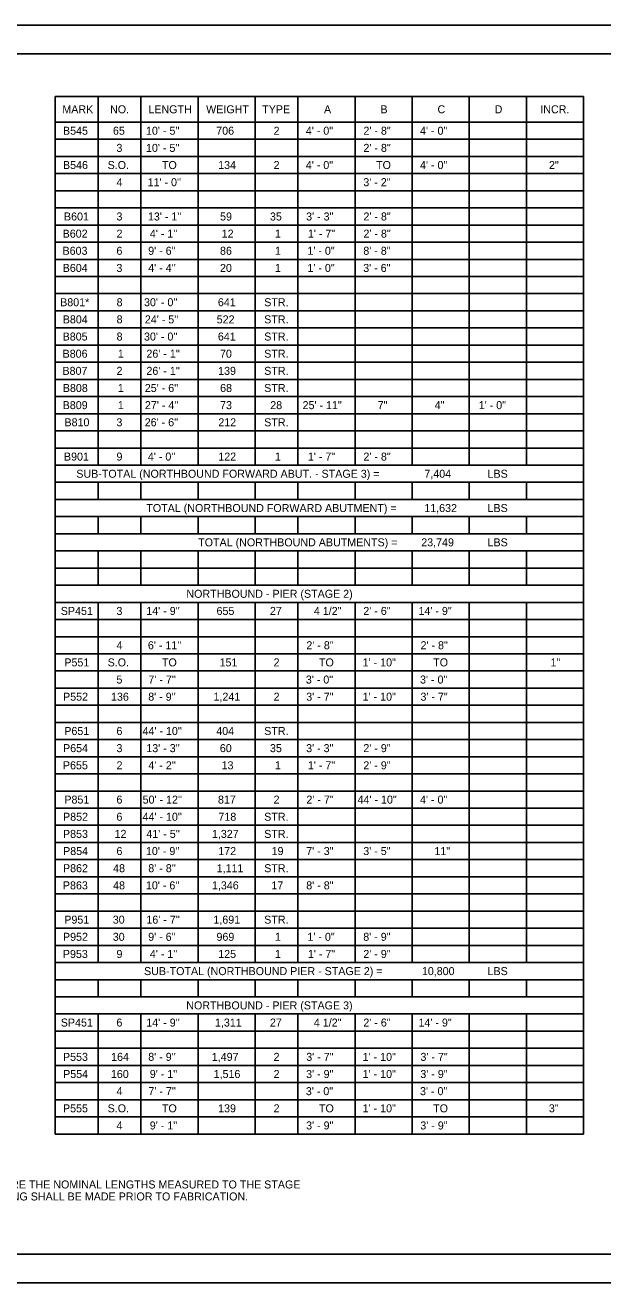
# Model space of a CAD drawing. Extents: x 1485751 to 1485785, y 230696.6 to 230718.6.
# Drawn here: x 1485763.13 to 1485773.25, y 230696.64 to 230718.64 of the extents above; entities that cross this region are included whole.
import ezdxf

# ---------------------------------------------------------------- set-up
doc = ezdxf.new("R2010")
doc.units = 0
for name, color, linetype in [('SH_Border', 7, 'Continuous'), ('SH_Cut_Line', 7, 'Continuous'), ('TX_P_Misc', 7, 'Continuous')]:
    doc.layers.add(name, color=color, linetype=linetype)

msp = doc.modelspace()

# ---------------------------------------------------------------- linework, layer by layer
at = {"layer": 'SH_Border'}
msp.add_lwpolyline([(1485753.033, 230718.141), (1485784.533, 230718.141), (1485784.533, 230697.141), (1485753.033, 230697.141)], close=True, dxfattribs=at)
at = {"layer": 'SH_Cut_Line'}
msp.add_lwpolyline([(1485751.033, 230718.641), (1485785.033, 230718.641), (1485785.033, 230696.641), (1485751.033, 230696.641)], close=True, dxfattribs=at)
at = {"layer": 'TX_P_Misc'}
for p, q in [((1485763.658, 230717.394), (1485772.908, 230717.394)), ((1485763.658, 230717.394), (1485763.658, 230699.244)), ((1485764.408, 230717.394), (1485764.408, 230710.944)), ((1485765.158, 230717.394), (1485765.158, 230710.944)), ((1485766.158, 230717.394), (1485766.158, 230710.944)), ((1485767.158, 230717.394), (1485767.158, 230710.944)), ((1485767.908, 230717.394), (1485767.908, 230710.944)), ((1485768.908, 230717.394), (1485768.908, 230710.944)), ((1485769.908, 230717.394), (1485769.908, 230710.944)), ((1485770.908, 230717.394), (1485770.908, 230710.944)), ((1485771.908, 230717.394), (1485771.908, 230710.944)), ((1485772.908, 230717.394), (1485772.908, 230699.244)), ((1485763.658, 230716.944), (1485772.908, 230716.944)), ((1485763.658, 230716.644), (1485772.908, 230716.644)), ((1485763.658, 230716.344), (1485772.908, 230716.344)), ((1485763.658, 230716.044), (1485772.908, 230716.044)), ((1485763.658, 230715.744), (1485772.908, 230715.744)), ((1485763.658, 230715.444), (1485772.908, 230715.444)), ((1485763.658, 230715.144), (1485772.908, 230715.144)), ((1485763.658, 230714.844), (1485772.908, 230714.844)), ((1485763.658, 230714.544), (1485772.908, 230714.544)), ((1485763.658, 230714.244), (1485772.908, 230714.244)), ((1485763.658, 230713.944), (1485772.908, 230713.944)), ((1485763.658, 230713.644), (1485772.908, 230713.644)), ((1485763.658, 230713.344), (1485772.908, 230713.344)), ((1485763.658, 230713.044), (1485772.908, 230713.044)), ((1485763.658, 230712.744), (1485772.908, 230712.744)), ((1485763.658, 230712.444), (1485772.908, 230712.444)), ((1485763.658, 230712.144), (1485772.908, 230712.144)), ((1485763.658, 230711.844), (1485772.908, 230711.844)), ((1485763.658, 230711.544), (1485772.908, 230711.544)), ((1485763.658, 230711.244), (1485772.908, 230711.244)), ((1485763.658, 230710.944), (1485772.908, 230710.944)), ((1485763.658, 230710.644), (1485772.908, 230710.644)), ((1485764.408, 230710.644), (1485764.408, 230710.344)), ((1485765.158, 230710.644), (1485765.158, 230710.344)), ((1485766.158, 230710.644), (1485766.158, 230710.344)), ((1485767.158, 230710.644), (1485767.158, 230710.344)), ((1485767.908, 230710.644), (1485767.908, 230710.344)), ((1485768.908, 230710.644), (1485768.908, 230710.344)), ((1485769.908, 230710.644), (1485769.908, 230710.344)), ((1485770.908, 230710.644), (1485770.908, 230710.344)), ((1485771.908, 230710.644), (1485771.908, 230710.344)), ((1485763.658, 230710.344), (1485772.908, 230710.344)), ((1485763.658, 230710.044), (1485772.908, 230710.044)), ((1485764.408, 230710.044), (1485764.408, 230709.744)), ((1485765.158, 230710.044), (1485765.158, 230709.744)), ((1485766.158, 230710.044), (1485766.158, 230709.744)), ((1485767.158, 230710.044), (1485767.158, 230709.744)), ((1485767.908, 230710.044), (1485767.908, 230709.744)), ((1485768.908, 230710.044), (1485768.908, 230709.744)), ((1485769.908, 230710.044), (1485769.908, 230709.744)), ((1485770.908, 230710.044), (1485770.908, 230709.744)), ((1485771.908, 230710.044), (1485771.908, 230709.744)), ((1485763.658, 230709.744), (1485772.908, 230709.744)), ((1485763.658, 230709.444), (1485772.908, 230709.444)), ((1485764.408, 230709.444), (1485764.408, 230708.844)), ((1485765.158, 230709.444), (1485765.158, 230708.844)), ((1485766.158, 230709.444), (1485766.158, 230708.844)), ((1485767.158, 230709.444), (1485767.158, 230708.844)), ((1485767.908, 230709.444), (1485767.908, 230708.844)), ((1485768.908, 230709.444), (1485768.908, 230708.844)), ((1485769.908, 230709.444), (1485769.908, 230708.844)), ((1485770.908, 230709.444), (1485770.908, 230708.844)), ((1485771.908, 230709.444), (1485771.908, 230708.844)), ((1485763.658, 230709.144), (1485772.908, 230709.144)), ((1485763.658, 230708.844), (1485772.908, 230708.844)), ((1485763.658, 230708.544), (1485772.908, 230708.544)), ((1485764.408, 230708.544), (1485764.408, 230702.244)), ((1485765.158, 230708.544), (1485765.158, 230702.244)), ((1485766.158, 230708.544), (1485766.158, 230702.244)), ((1485767.158, 230708.544), (1485767.158, 230702.244)), ((1485767.908, 230708.544), (1485767.908, 230702.244)), ((1485768.908, 230708.544), (1485768.908, 230702.244)), ((1485769.908, 230708.544), (1485769.908, 230702.244)), ((1485770.908, 230708.544), (1485770.908, 230702.244)), ((1485771.908, 230708.544), (1485771.908, 230702.244)), ((1485763.658, 230708.244), (1485772.908, 230708.244)), ((1485763.658, 230707.944), (1485772.908, 230707.944)), ((1485763.658, 230707.644), (1485772.908, 230707.644)), ((1485763.658, 230707.344), (1485772.908, 230707.344)), ((1485763.658, 230707.044), (1485772.908, 230707.044)), ((1485763.658, 230706.744), (1485772.908, 230706.744)), ((1485763.658, 230706.444), (1485772.908, 230706.444)), ((1485763.658, 230706.144), (1485772.908, 230706.144)), ((1485763.658, 230705.844), (1485772.908, 230705.844)), ((1485763.658, 230705.544), (1485772.908, 230705.544)), ((1485763.658, 230705.244), (1485772.908, 230705.244)), ((1485763.658, 230704.944), (1485772.908, 230704.944)), ((1485763.658, 230704.644), (1485772.908, 230704.644)), ((1485763.658, 230704.344), (1485772.908, 230704.344)), ((1485763.658, 230704.044), (1485772.908, 230704.044)), ((1485763.658, 230703.744), (1485772.908, 230703.744)), ((1485763.658, 230703.444), (1485772.908, 230703.444)), ((1485763.658, 230703.144), (1485772.908, 230703.144)), ((1485763.658, 230702.844), (1485772.908, 230702.844)), ((1485763.658, 230702.544), (1485772.908, 230702.544)), ((1485763.658, 230702.244), (1485772.908, 230702.244)), ((1485763.658, 230701.944), (1485772.908, 230701.944)), ((1485764.408, 230701.944), (1485764.408, 230701.644)), ((1485765.158, 230701.944), (1485765.158, 230701.644)), ((1485766.158, 230701.944), (1485766.158, 230701.644)), ((1485767.158, 230701.944), (1485767.158, 230701.644)), ((1485767.908, 230701.944), (1485767.908, 230701.644)), ((1485768.908, 230701.944), (1485768.908, 230701.644)), ((1485769.908, 230701.944), (1485769.908, 230701.644)), ((1485770.908, 230701.944), (1485770.908, 230701.644)), ((1485771.908, 230701.944), (1485771.908, 230701.644)), ((1485763.658, 230701.644), (1485772.908, 230701.644)), ((1485763.658, 230701.344), (1485772.908, 230701.344)), ((1485764.408, 230701.344), (1485764.408, 230699.244)), ((1485765.158, 230701.344), (1485765.158, 230699.244)), ((1485766.158, 230701.344), (1485766.158, 230699.244)), ((1485767.158, 230701.344), (1485767.158, 230699.244)), ((1485767.908, 230701.344), (1485767.908, 230699.244)), ((1485768.908, 230701.344), (1485768.908, 230699.244)), ((1485769.908, 230701.344), (1485769.908, 230699.244)), ((1485770.908, 230701.344), (1485770.908, 230699.244)), ((1485771.908, 230701.344), (1485771.908, 230699.244)), ((1485763.658, 230701.044), (1485772.908, 230701.044)), ((1485763.658, 230700.744), (1485772.908, 230700.744)), ((1485763.658, 230700.444), (1485772.908, 230700.444)), ((1485763.658, 230700.144), (1485772.908, 230700.144)), ((1485763.658, 230699.844), (1485772.908, 230699.844)), ((1485763.658, 230699.544), (1485772.908, 230699.544)), ((1485763.658, 230699.244), (1485772.908, 230699.244))]:
    msp.add_line(p, q, dxfattribs=at)

# ---------------------------------------------------------------- texts
for s, p in [('MARK', (1485763.782, 230717.099)), ('NO.', (1485764.618, 230717.099)), ('LENGTH', (1485765.288, 230717.099)), ('WEIGHT', (1485766.3, 230717.099)), ('TYPE', (1485767.282, 230717.099)), ('A', (1485768.364, 230717.099)), ('B', (1485769.353, 230717.099)), ('C', (1485770.352, 230717.099)), ('D', (1485771.353, 230717.099)), ('INCR.', (1485772.152, 230717.099)), ('B545', (1485763.793, 230716.724)), ('65', (1485764.668, 230716.724)), ("10' - 5''", (1485765.247, 230716.724)), ('706', (1485766.477, 230716.724)), ('2', (1485767.481, 230716.724)), ('4\' - 0"', (1485768.046, 230716.724)), ('2\' - 8"', (1485769.055, 230716.724)), ('4\' - 0"', (1485770.046, 230716.724)), ('3', (1485764.729, 230716.424)), ("10' - 5''", (1485765.247, 230716.424)), ('2\' - 8"', (1485769.055, 230716.424)), ('B546', (1485763.793, 230716.124)), ('S.O.', (1485764.575, 230716.124)), ('TO', (1485765.526, 230716.124)), ('134', (1485766.511, 230716.124)), ('2', (1485767.481, 230716.124)), ('4\' - 0"', (1485768.046, 230716.124)), ('TO', (1485769.276, 230716.124)), ('4\' - 0"', (1485770.046, 230716.124)), (' 2"', (1485772.252, 230716.124)), ('4', (1485764.731, 230715.824)), ("11' - 0''", (1485765.275, 230715.824)), ('3\' - 2"', (1485769.053, 230715.824)), ('B601', (1485763.81, 230715.224)), ('3', (1485764.729, 230715.224)), ("13' - 1''", (1485765.28, 230715.224)), ('59', (1485766.544, 230715.224)), ('35', (1485767.418, 230715.224)), ('3\' - 3"', (1485768.051, 230715.224)), ('2\' - 8"', (1485769.055, 230715.224)), ('B602', (1485763.787, 230714.924)), ('2', (1485764.731, 230714.924)), ("4' - 1''", (1485765.314, 230714.924)), ('12', (1485766.572, 230714.924)), ('1', (1485767.504, 230714.924)), ('1\' - 7"', (1485768.082, 230714.924)), ('2\' - 8"', (1485769.055, 230714.924)), ('B603', (1485763.785, 230714.624)), ('6', (1485764.729, 230714.624)), ("9' - 6''", (1485765.285, 230714.624)), ('86', (1485766.543, 230714.624)), ('1', (1485767.504, 230714.624)), ('1\' - 0"', (1485768.074, 230714.624)), ('8\' - 8"', (1485769.053, 230714.624)), ('B604', (1485763.788, 230714.324)), ('3', (1485764.729, 230714.324)), ("4' - 4''", (1485765.286, 230714.324)), ('20', (1485766.543, 230714.324)), ('1', (1485767.504, 230714.324)), ('1\' - 0"', (1485768.074, 230714.324)), ('3\' - 6"', (1485769.051, 230714.324)), ('B801*', (1485763.743, 230713.724)), ('8', (1485764.732, 230713.724)), ("30' - 0''", (1485765.212, 230713.724)), ('641', (1485766.506, 230713.724)), ('STR.', (1485767.317, 230713.724)), ('B804', (1485763.789, 230713.424)), ('8', (1485764.732, 230713.424)), ("24' - 5''", (1485765.227, 230713.424)), ('522', (1485766.485, 230713.424)), ('STR.', (1485767.317, 230713.424)), ('B805', (1485763.787, 230713.124)), ('8', (1485764.732, 230713.124)), ("30' - 0''", (1485765.212, 230713.124)), ('641', (1485766.506, 230713.124)), ('STR.', (1485767.317, 230713.124)), ('B806', (1485763.786, 230712.824)), ('1', (1485764.754, 230712.824)), ("26' - 1''", (1485765.254, 230712.824)), ('70', (1485766.543, 230712.824)), ('STR.', (1485767.317, 230712.824)), ('B807', (1485763.784, 230712.524)), ('2', (1485764.731, 230712.524)), ("26' - 1''", (1485765.254, 230712.524)), ('139', (1485766.51, 230712.524)), ('STR.', (1485767.317, 230712.524)), ('B808', (1485763.79, 230712.224)), ('1', (1485764.754, 230712.224)), ("25' - 6''", (1485765.226, 230712.224)), ('68', (1485766.545, 230712.224)), ('STR.', (1485767.317, 230712.224)), ('B809', (1485763.788, 230711.924)), ('1', (1485764.754, 230711.924)), ("27' - 4''", (1485765.228, 230711.924)), ('73', (1485766.544, 230711.924)), ('28', (1485767.423, 230711.924)), ('25\' - 11"', (1485767.989, 230711.924)), (' 7"', (1485769.252, 230711.924)), (' 4"', (1485770.251, 230711.924)), ('1\' - 0"', (1485771.074, 230711.924)), ('B810', (1485763.819, 230711.624)), ('3', (1485764.729, 230711.624)), ("26' - 6''", (1485765.225, 230711.624)), ('212', (1485766.513, 230711.624)), ('STR.', (1485767.317, 230711.624)), ('B901', (1485763.81, 230711.024)), ('9', (1485764.73, 230711.024)), ("4' - 0''", (1485765.28, 230711.024)), ('122', (1485766.513, 230711.024)), ('1', (1485767.504, 230711.024)), ('1\' - 7"', (1485768.082, 230711.024)), ('2\' - 8"', (1485769.055, 230711.024)), ('SUB-TOTAL (NORTHBOUND FORWARD ABUT. - STAGE 3) =', (1485764.026, 230710.724)), ('7,404', (1485770.122, 230710.724)), ('LBS', (1485771.228, 230710.724)), ('TOTAL (NORTHBOUND FORWARD ABUTMENT) =', (1485765.252, 230710.124)), ('11,632', (1485770.12, 230710.124)), ('LBS', (1485771.228, 230710.124)), ('TOTAL (NORTHBOUND ABUTMENTS) =', (1485766.161, 230709.524)), ('23,749', (1485770.067, 230709.524)), ('LBS', (1485771.228, 230709.524)), ('NORTHBOUND - PIER (STAGE 2)', (1485765.954, 230708.624)), ('SP451', (1485763.755, 230708.324)), ('3', (1485764.729, 230708.324)), ("14' - 9''", (1485765.252, 230708.324)), ('655', (1485766.482, 230708.324)), ('27', (1485767.417, 230708.324)), (' 4 1/2"', (1485768.135, 230708.324)), ('2\' - 6"', (1485769.053, 230708.324)), ('14\' - 9"', (1485770.019, 230708.324)), ('4', (1485764.731, 230707.724)), ("6' - 11''", (1485765.28, 230707.724)), ('2\' - 8"', (1485768.055, 230707.724)), ('2\' - 8"', (1485770.055, 230707.724)), ('P551', (1485763.817, 230707.424)), ('S.O.', (1485764.575, 230707.424)), ('TO', (1485765.526, 230707.424)), ('151', (1485766.535, 230707.424)), ('2', (1485767.481, 230707.424)), ('TO', (1485768.276, 230707.424)), ('1\' - 10"', (1485769.041, 230707.424)), ('TO', (1485770.276, 230707.424)), (' 1"', (1485772.279, 230707.424)), ('5', (1485764.729, 230707.124)), ("7' - 7''", (1485765.289, 230707.124)), ('3\' - 0"', (1485768.046, 230707.124)), ('3\' - 0"', (1485770.046, 230707.124)), ('P552', (1485763.794, 230706.824)), ('136', (1485764.634, 230706.824)), ("8' - 9''", (1485765.286, 230706.824)), ('1,241', (1485766.429, 230706.824)), ('2', (1485767.481, 230706.824)), ('3\' - 7"', (1485768.053, 230706.824)), ('1\' - 10"', (1485769.041, 230706.824)), ('3\' - 7"', (1485770.053, 230706.824)), ('P651', (1485763.816, 230706.224)), ('6', (1485764.729, 230706.224)), ("44' - 10''", (1485765.186, 230706.224)), ('404', (1485766.478, 230706.224)), ('STR.', (1485767.317, 230706.224)), ('P654', (1485763.794, 230705.924)), ('3', (1485764.729, 230705.924)), ("13' - 3''", (1485765.252, 230705.924)), ('60', (1485766.54, 230705.924)), ('35', (1485767.418, 230705.924)), ('3\' - 3"', (1485768.051, 230705.924)), ('2\' - 9"', (1485769.053, 230705.924)), ('P655', (1485763.792, 230705.624)), ('2', (1485764.731, 230705.624)), ("4' - 2''", (1485765.288, 230705.624)), ('13', (1485766.571, 230705.624)), ('1', (1485767.504, 230705.624)), ('1\' - 7"', (1485768.082, 230705.624)), ('2\' - 9"', (1485769.053, 230705.624)), ('P851', (1485763.817, 230705.024)), ('6', (1485764.729, 230705.024)), ("50' - 12''", (1485765.188, 230705.024)), ('817', (1485766.507, 230705.024)), ('2', (1485767.481, 230705.024)), ('2\' - 7"', (1485768.056, 230705.024)), ('44\' - 10"', (1485768.952, 230705.024)), ('4\' - 0"', (1485770.046, 230705.024)), ('P852', (1485763.794, 230704.724)), ('6', (1485764.729, 230704.724)), ("44' - 10''", (1485765.186, 230704.724)), ('718', (1485766.515, 230704.724)), ('STR.', (1485767.317, 230704.724)), ('P853', (1485763.793, 230704.424)), ('12', (1485764.697, 230704.424)), ("41' - 5''", (1485765.253, 230704.424)), ('1,327', (1485766.401, 230704.424)), ('STR.', (1485767.317, 230704.424)), ('P854', (1485763.795, 230704.124)), ('6', (1485764.729, 230704.124)), ("10' - 9''", (1485765.246, 230704.124)), ('172', (1485766.513, 230704.124)), ('19', (1485767.447, 230704.124)), ('7\' - 3"', (1485768.053, 230704.124)), ('3\' - 5"', (1485769.052, 230704.124)), (' 11"', (1485770.246, 230704.124)), ('P862', (1485763.793, 230703.824)), ('48', (1485764.671, 230703.824)), ("8' - 8''", (1485765.287, 230703.824)), ('1,111', (1485766.484, 230703.824)), ('STR.', (1485767.317, 230703.824)), ('P863', (1485763.791, 230703.524)), ('48', (1485764.671, 230703.524)), ("10' - 6''", (1485765.246, 230703.524)), ('1,346', (1485766.402, 230703.524)), ('17', (1485767.443, 230703.524)), ('8\' - 8"', (1485768.053, 230703.524)), ('P951', (1485763.816, 230702.924)), ('30', (1485764.665, 230702.924)), ("16' - 7''", (1485765.254, 230702.924)), ('1,691', (1485766.427, 230702.924)), ('STR.', (1485767.317, 230702.924)), ('P952', (1485763.793, 230702.624)), ('30', (1485764.665, 230702.624)), ("9' - 6''", (1485765.285, 230702.624)), ('969', (1485766.481, 230702.624)), ('1', (1485767.504, 230702.624)), ('1\' - 0"', (1485768.074, 230702.624)), ('8\' - 9"', (1485769.052, 230702.624)), ('P953', (1485763.791, 230702.324)), ('9', (1485764.73, 230702.324)), ("4' - 1''", (1485765.314, 230702.324)), ('125', (1485766.512, 230702.324)), ('1', (1485767.504, 230702.324)), ('1\' - 7"', (1485768.082, 230702.324)), ('2\' - 9"', (1485769.053, 230702.324)), ('SUB-TOTAL (NORTHBOUND PIER - STAGE 2) =', (1485765.213, 230702.024)), ('10,800', (1485770.078, 230702.024)), ('LBS', (1485771.228, 230702.024)), ('NORTHBOUND - PIER (STAGE 3)', (1485765.952, 230701.424)), ('SP451', (1485763.755, 230701.124)), ('6', (1485764.729, 230701.124)), ("14' - 9''", (1485765.252, 230701.124)), ('1,311', (1485766.455, 230701.124)), ('27', (1485767.417, 230701.124)), (' 4 1/2"', (1485768.135, 230701.124)), ('2\' - 6"', (1485769.053, 230701.124)), ('14\' - 9"', (1485770.019, 230701.124)), ('P553', (1485763.793, 230700.524)), ('164', (1485764.636, 230700.524)), ("8' - 9''", (1485765.286, 230700.524)), ('1,497', (1485766.399, 230700.524)), ('2', (1485767.481, 230700.524)), ('3\' - 7"', (1485768.053, 230700.524)), ('1\' - 10"', (1485769.041, 230700.524)), ('3\' - 7"', (1485770.053, 230700.524)), ('P554', (1485763.795, 230700.224)), ('160', (1485764.632, 230700.224)), ("9' - 1''", (1485765.313, 230700.224)), ('1,516', (1485766.431, 230700.224)), ('2', (1485767.481, 230700.224)), ('3\' - 9"', (1485768.051, 230700.224)), ('1\' - 10"', (1485769.041, 230700.224)), ('3\' - 9"', (1485770.051, 230700.224)), ('4', (1485764.731, 230699.924)), ("7' - 7''", (1485765.289, 230699.924)), ('3\' - 0"', (1485768.046, 230699.924)), ('3\' - 0"', (1485770.046, 230699.924)), ('P555', (1485763.793, 230699.624)), ('S.O.', (1485764.575, 230699.624)), ('TO', (1485765.526, 230699.624)), ('139', (1485766.51, 230699.624)), ('2', (1485767.481, 230699.624)), ('TO', (1485768.276, 230699.624)), ('1\' - 10"', (1485769.041, 230699.624)), ('TO', (1485770.276, 230699.624)), (' 3"', (1485772.25, 230699.624)), ('4', (1485764.731, 230699.324)), ("9' - 1''", (1485765.313, 230699.324)), ('3\' - 9"', (1485768.051, 230699.324)), ('3\' - 9"', (1485770.051, 230699.324)), ('* - INDICATES BARS REQUIRING MECHANICAL CONNECTORS.  THE LENGTHS SHOWN IN THE TABLE ARE THE NOMINAL LENGTHS MEASURED TO THE STAGE', (1485753.586, 230698.292)), ('    CONSTRUCTION JOINT.  ADJUSTMENT IN THE LENGTHS OF THE BARS DUE TO MECHANICAL SPLICING SHALL BE MADE PRIOR TO FABRICATION.', (1485753.586, 230698.082))]:
    msp.add_text(s, height=0.14, dxfattribs=at).set_placement(p)

doc.saveas('drawing.dxf')
